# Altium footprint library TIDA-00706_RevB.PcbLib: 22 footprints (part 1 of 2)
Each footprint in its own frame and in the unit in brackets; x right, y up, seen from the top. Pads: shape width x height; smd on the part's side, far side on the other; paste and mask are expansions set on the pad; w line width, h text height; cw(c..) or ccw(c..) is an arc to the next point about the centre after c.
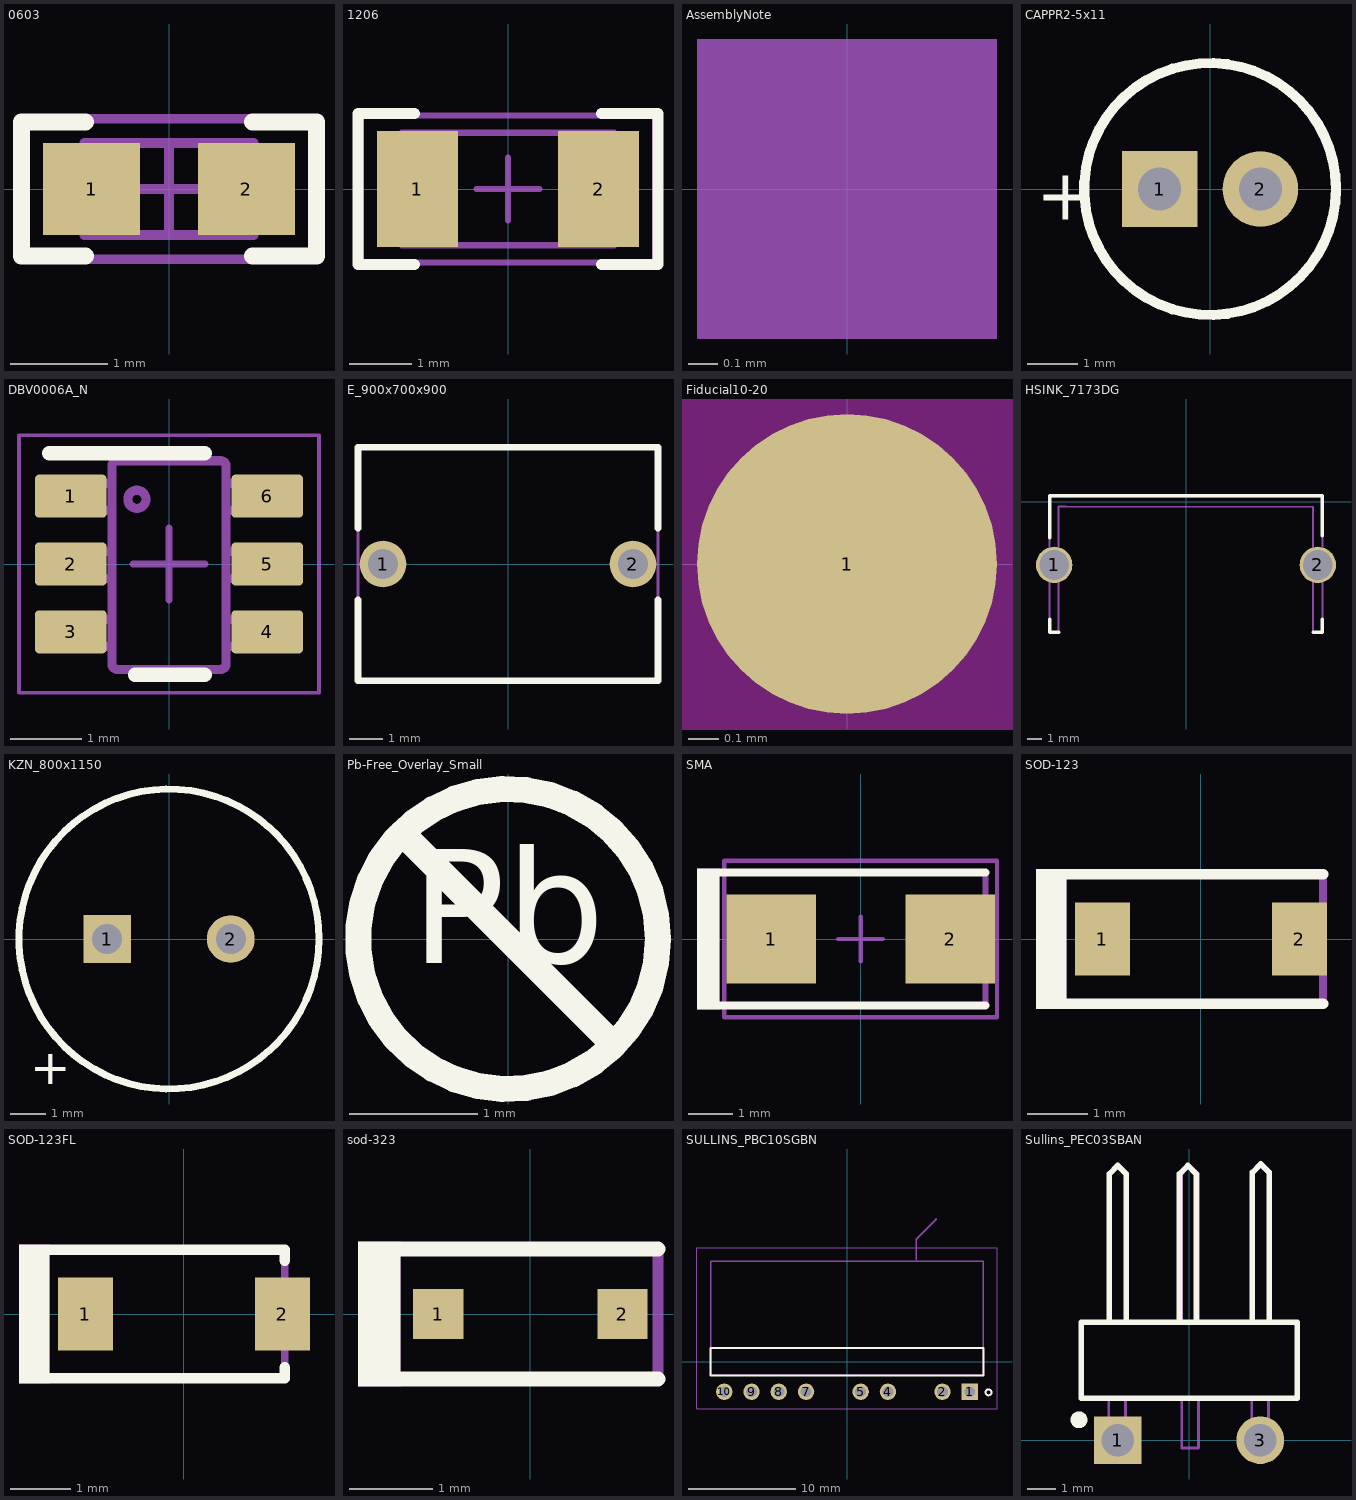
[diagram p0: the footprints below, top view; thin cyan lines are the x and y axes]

## 0603 [mm] "0603 from SM-752 data"
height 1
pads (2):
  rect 1x0.95 smd: 1(-0.8,0) 2(0.8,0)
Top Overlay:
  lines w0.178: -0.864,-0.691 -1.524,-0.691 -1.524,0.693 -0.864,0.693 ; 0.864,-0.691 1.524,-0.691 1.524,0.693 0.864,0.693
Mechanical 5:
  lines w0.1: -1.55,-0.725 1.55,-0.725 1.55,0.725 -1.55,0.725 -1.55,-0.725
  text ".Designator" at -0.991,-0.381 h0.76
Mechanical 13:
  lines w0.1: -0.55,-0.475 -0.55,0.475 ; 0.55,-0.475 0.55,0.475 ; -0.875,-0.475 -0.875,0.475 0.875,0.475 0.875,-0.475 -0.875,-0.475
Mechanical 15:
  lines w0.1: -0.475,0 0.475,0 ; 0,-0.475 0,0.475 ; -1.55,-0.725 -1.55,0.725 1.55,0.725 1.55,-0.725 -1.55,-0.725
3D body: height 1, standoff 0, extent 0.551,-0.474 0.874,0.474
3D body: height 1, standoff 0, extent -0.549,-0.474 0.549,0.474
3D body: height 1, standoff 0, extent -0.874,-0.474 -0.551,0.474

## 1206 [mm] "1206 from SM-752 data"
height 1.35
pads (2):
  rect 1.3x1.85 smd: 1(-1.45,0) 2(1.45,0)
Top Overlay:
  lines w0.178: -1.5,-1.21 -2.4,-1.21 -2.4,1.21 -1.5,1.21 ; 1.5,-1.21 2.4,-1.21 2.4,1.21 1.5,1.21
Mechanical 5:
  lines w0.1: -1.7,-0.9 -1.7,0.9 1.7,0.9 1.7,-0.9 -1.7,-0.9
  text ".Designator" at -0.965,-0.457 h0.76
Mechanical 13:
  lines w0.1: -1.2,-0.9 -1.2,0.9 ; 1.2,-0.9 1.2,0.9 ; -1.7,-0.9 -1.7,0.9 1.7,0.9 1.7,-0.9 -1.7,-0.9
Mechanical 15:
  lines w0.1: -0.5,0 0.5,0 ; 0,-0.5 0,0.5 ; -2.35,-1.175 -2.35,1.175 2.35,1.175 2.35,-1.175 -2.35,-1.175
3D body: height 1.35, standoff 0, extent 1.201,-0.899 1.699,0.899
3D body: height 1.35, standoff 0, extent -1.199,-0.899 1.199,0.899
3D body: height 1.35, standoff 0, extent -1.699,-0.899 -1.201,0.899

## AssemblyNote [mm] "Assembly Note"
Mechanical 5:
  rectangle: -0.508,-0.508 0.508,0.508
  text ".Comment" at 1.143,-0.508 h0.76
  text ".Designator" at -4.191,-0.508 h0.76

## CAPPR2-5x11 [mm] "Capacitor, Electrolytic, Radial; Body 5 x 11 mm (Dia.xH typ); Pin Spacing 2 mm (typ)"
height 11.5
pads (2):
  rect 1.5x1.5 hole 0.85: 1(-1,0)
  round 1.5 hole 0.85: 2(1,0)
Top Overlay:
  circle w0.2: c0,0 r2.5
  text "+" at -3.454,-0.61 h1.02
Mechanical 5:
  circle w0.127: c0,0 r2.5
  text "+" at -3.353,-0.533 h1.02
  text ".Designator" at 0.61,0.254 h0.76
3D body: height 11.29, standoff -3.51, extent -2.525,-2.527 2.526,2.523

## DBV0006A_N [mm] "SOT23, 6-Leads, Body 2.9x1.6mm, Pitch 0.95mm, Lead Span 2.8mm, IPC Medium Density"
height 1.45
pads (6):
  rrect17% 1x0.6 smd: 1(-1.375,0.95) 2(-1.375,0) 3(-1.375,-0.95) 4(1.375,-0.95) 5(1.375,0) 6(1.375,0.95)
Top Overlay:
  lines w0.2: -1.675,1.55 0.5,1.55 ; -0.475,-1.55 0.5,-1.55
Mechanical 5:
  lines w0.127: 0.724,-1.475 ccw(c0.723,-1.399) 0.8,-1.399 0.799,1.37 ccw(c0.723,1.37) 0.724,1.446 ; 0.723,-1.475 -0.725,-1.475 -0.725,-1.475 cw(c-0.724,-1.399) -0.801,-1.399 -0.801,1.37 cw(c-0.724,1.37) -0.725,1.446 -0.725,1.446 0.723,1.446 ; 0.723,-1.475 0.724,-1.475 ; 0.723,1.446 0.724,1.446 ; -1.423,-1.154 -1.423,-0.78 -1.206,-0.78 -1.113,-0.78 -1.081,-0.78 -0.828,-0.78 -0.801,-0.78 -0.801,-1.154 -0.828,-1.154 -1.081,-1.154 -1.113,-1.154 -1.206,-1.154 -1.423,-1.154 ; -1.423,-0.202 -1.423,0.173 -1.206,0.173 -1.113,0.173 -1.081,0.173 -0.828,0.173 -0.801,0.173 -0.801,-0.202 -0.828,-0.202 -1.081,-0.202 -1.113,-0.202 -1.206,-0.202 -1.423,-0.202 ; -1.423,0.751 -1.423,1.125 -1.206,1.125 -1.113,1.125 -1.081,1.125 -0.828,1.125 -0.801,1.125 -0.801,0.751 -0.828,0.751 -1.081,0.751 -1.113,0.751 -1.206,0.751 -1.423,0.751 ; -0.577,0.906 ccw(c-0.45,0.906) -0.323,0.906 ccw(c-0.45,0.906) -0.577,0.906 ; 0.799,-1.154 0.799,-0.78 0.827,-0.78 1.08,-0.78 1.112,-0.78 1.205,-0.78 1.422,-0.78 1.422,-1.154 1.205,-1.154 1.112,-1.154 1.08,-1.154 0.827,-1.154 0.799,-1.154 ; 0.799,-0.202 0.799,0.173 0.827,0.173 1.08,0.173 1.112,0.173 1.205,0.173 1.422,0.173 1.422,-0.202 1.205,-0.202 1.112,-0.202 1.08,-0.202 0.827,-0.202 0.799,-0.202 ; 0.799,0.751 0.799,1.125 0.827,1.125 1.08,1.125 1.112,1.125 1.205,1.125 1.422,1.125 1.422,0.751 1.205,0.751 1.112,0.751 1.08,0.751 0.827,0.751 0.799,0.751
  text ".Designator" at -0.317,0.432 h0.76
Mechanical 15:
  lines w0.05: -2.1,-1.8 -2.1,1.8 2.1,1.8 2.1,-1.8 -2.1,-1.8
  lines w0.1: -0.5,0 0.5,0 ; 0,-0.5 0,0.5
3D body: height 1.12, standoff 0, extent -1.422,-1.46 1.423,1.461

## E_900x700x900 [mm] "TH, 2- Leads, Body 9x7mm, Pin Spacing 7.5mm"
height 12
pads (2):
  round 1.4 hole 0.9: 1(-3.75,0) 2(3.75,0)
Top Overlay:
  lines w0.2: -4.5,-1.071 -4.5,-3.5 4.5,-3.5 4.5,-1.071 ; -4.5,1.071 -4.5,3.5 4.5,3.5 4.5,1.071
Mechanical 5:
  lines w0.1: -4.5,-3.5 4.5,-3.5 4.5,3.5 -4.5,3.5 -4.5,-3.5
  text ".Designator" at -1.397,-0.406 h0.76
3D body: height 0.3, standoff -2.5, extent -4.047,-0.299 -3.45,0.3
3D body: height 1.36, standoff -0.16, extent -4.047,-1.732 -3.45,0.3
3D body: height 6.12, standoff 0.81, extent -4.047,-1.732 -1.545,-1.033
3D body: height 6.12, standoff 0.81, extent 1.546,1.033 4.048,1.732
3D body: height 1.36, standoff -0.16, extent 3.45,-0.299 4.048,1.732
3D body: height 0.3, standoff -2.5, extent 3.45,-0.299 4.048,0.299
3D body: height 11.96, standoff 3, extent -4.491,-3.5 4.491,3.5

## Fiducial10-20 [mm]
pads (1):
  round 1 smd mask+0.5: 1(0,0)
Top Layer keep-out:
  circle w1.178: c0,0 r0.5

## HSINK_7173DG [mil] "Aavid"
height 900
pads (2):
  round 100 hole 82: 1(-362.5,-173.23) 2(362.5,-173.23)
Top Overlay:
  lines w10: -375,-323.23 -375,-358.23 -350,-358.23 ; -375,-98.23 -375,16.77 375,16.77 375,-93.23 ; 350,-358.23 375,-358.23 375,-323.23
Mechanical 5:
  lines w5: -375,-358.27 -375,14.27 375,14.27 375,-358.27 349.41,-358.27 349.41,-82.68 349.41,-13.78 -329.72,-12.8 -350.39,-12.8 -350.39,-31.5 -350.39,-358.27 -375,-358.27
  text ".Designator" at -19,23 h30
3D body: height 150, standoff 0, extent 349.81,-247.74 374.81,-97.74
3D body: height 150, standoff 0, extent -375,-248.23 -350,-98.23
3D body: height 0, standoff -100, extent 349.49,-192.99 375.15,-155.49
3D body: height 0, standoff -100, extent -375.24,-190.73 -349.59,-153.23
3D body: height 900, standoff 150, extent -375.49,-358.23 375.3,12.26

## KZN_800x1150 [mm] "TH, 2-Leads, Dia 8mm"
height 13
pads (2):
  rect 1.35x1.35 hole 0.85: 1(-1.75,0)
  round 1.35 hole 0.85: 2(1.75,0)
Top Overlay:
  circle w0.2: c0,0 r4.25
  text "+" at -3.937,-4.115 h1
  text "+" at -3.937,-4.115 h1
Mechanical 5:
  circle w0.1: c0,0 r4.25
  text ".Designator" at -0.838,-0.33 h0.76
  text "+" at -4.064,3.048 h1.02
  text "+" at -4.064,3.048 h1.02
3D body: height 0, standoff -2, extent 1.453,-0.299 2.05,0.3
3D body: height 0, standoff -2.5, extent -2.047,-0.299 -1.45,0.3
3D body: height 13.01, standoff -4, extent -4.217,-4.243 4.244,4.243

## Pb-Free_Overlay_Small [mm]
Top Overlay:
  circle w0.203: c0,0 r1.168
  lines w0.203: -0.826,0.826 0.826,-0.826
  text "Pb" at -0.752,-0.48 h1.52

## SMA [mm] "Molded Diode, 2-Leads, Body 4.3x2.6mm, IPC Medium Density, based on OnSemi component dimensions and land pattern"
height 2.27
pads (2):
  rect 2x2 smd: 1(-2,0) 2(2,0)
Top Overlay:
  rectangle: -3.658,-1.575 -3.15,1.575
  lines w0.178: -3.327,-1.486 2.794,-1.486 ; -3.327,1.486 2.794,1.486
Mechanical 5:
  rectangle: -3.658,-1.575 -3.15,1.575
  lines w0.127: -3.327,-1.486 2.794,-1.486 2.794,1.486 -3.327,1.486
  text ".Designator" at -1.168,-0.508 h0.76
Mechanical 15:
  lines w0.1: -0.5,0 0.5,0 ; 0,-0.5 0,0.5 ; -3.05,-1.75 -3.05,1.75 3.05,1.75 3.05,-1.75 -3.05,-1.75
3D body: height 2.42, standoff 0.02, extent -2.6,-1.3 2.6,1.3

## SOD-123 [mm] "On Semi recommended land pattern"
height 1.35
pads (2):
  rect 0.915x1.22 smd: 1(-1.637,0) 2(1.637,0)
Top Overlay:
  rectangle: -2.743,-1.168 -2.235,1.168
  lines w0.178: -2.413,-1.079 2.032,-1.079 ; -2.413,1.079 2.032,1.079
Mechanical 5:
  rectangle: -2.743,-1.168 -2.235,1.168
  lines w0.127: -2.413,-1.079 2.032,-1.079 2.032,1.079 -2.413,1.079
  text ".Designator" at -1.372,-0.279 h0.76
3D body: height 1.35, standoff 0, extent -1.932,-0.9 1.932,0.9

## SOD-123FL [mm] "Copied from SOD-123"
height 0.991
pads (2):
  rect 0.915x1.22 smd: 1(-1.637,0) 2(1.637,0)
Top Overlay:
  rectangle: -2.743,-1.156 -2.235,1.156
  lines w0.178: -2.438,-1.067 1.676,-1.067 1.676,-0.889 ; -2.438,1.067 1.676,1.067 1.676,0.889
Mechanical 5:
  rectangle: -2.743,-1.156 -2.235,1.156
  lines w0.127: -2.438,-1.067 1.676,-1.067 1.676,1.067 -2.438,1.067
  text ".Designator" at -1.422,-0.305 h0.76
3D body: height 1, standoff 0, extent -1.9,-0.9 1.9,0.9

## sod-323 [mm] "NXP recommended land pattern"
height 1.15
pads (2):
  rect 0.6x0.6 smd paste-0.05: 1(-1.1,0) 2(1.1,0)
Top Overlay:
  rectangle: -2.057,-0.864 -1.549,0.864
  lines w0.178: -1.803,-0.775 0.1,-0.775 1.525,-0.775 ; -1.803,0.775 0.1,0.775 1.525,0.775
Mechanical 5:
  rectangle: -2.057,-0.864 -1.549,0.864
  lines w0.127: -1.803,-0.775 0.1,-0.775 1.525,-0.775 1.525,0.775 0.1,0.775 -1.803,0.775
  text ".Designator" at 0.432,0.305 h0.76
3D body: height 1.1, standoff 0, extent -1.3,-0.675 1.3,0.675

## SULLINS_PBC10SGBN [mil] "CONN,MALE-10PIN 2.54MM PITCH,SINGLEROW,SULLINS"
height 145.28
pads (10):
  rect 60x60 / inner round 60 / far side rect 60x60 hole 40: 1(450,-109.84)
  round 60 hole 40: 2(350,-109.84) 4(150,-109.84) 5(50,-109.84) 7(-150,-109.84) 8(-250,-109.84) 9(-350,-109.84) 10(-450,-109.84)
  round 0 all layers, no hole mask+0: 3(250,-109.84) 6(-50,-109.84)
Top Overlay:
  circle w7: c519,-112 r11
  lines w7.01: -500,-50 500,-50 500,50 -500,50 -500,-50
Bottom Overlay:
  lines w7: -473.63,50.16 -434.26,50.16 ; -400.89,-50 -361.52,-50 ; -394.89,50.16 -355.52,50.16 ; -316.15,50.16 -276.78,50.16 ; -243.41,-50 -204.04,-50 ; -237.41,50.16 -198.04,50.16 ; -164.67,-50 -125.3,-50 ; -158.67,50.16 -119.3,50.16 ; -85.93,-50 -46.56,-50 ; -79.93,50.16 -40.56,50.16 ; -7.19,-50 32.18,-50 ; -1.19,50.16 38.18,50.16 ; 71.55,-50 110.92,-50 ; 77.55,50.16 116.92,50.16 ; 150.29,-50 189.66,-50 ; 156.29,50.16 195.66,50.16 ; 229.03,-50 268.4,-50 ; 235.03,50.16 274.4,50.16 ; 307.77,-50 347.14,-50 ; 313.77,50.16 353.14,50.16 ; 386.51,-50 425.88,-50 ; 392.51,50.16 431.88,50.16 ; 500,-19.21 500,20.16
Mechanical 5:
  circle w5: c450,-109.84 r11
  lines w5: -500,-50 500,-50 500,50 ; -500,-49.61 -500,50 ; -500,50 500,50 ; -500,50 -500,368.11 500.01,368.11 500.01,50.01
  text ".Designator" at 134,7 h30
Mechanical 15:
  lines w1.97: -550,-172.52 -550,418.11 550,418.11 550,-172.52 -550,-172.52
Mechanical 16:
  lines w7: 254,374.16 254,450.16 327,523.16
Mechanical 17:
  text "PCE EDGE THIS SIDE" at 337,517.16 h40
  text "LEAD LENGTH:5.08MM" at -327,74.16 h40
3D body: height 141.73, standoff -198.27, extent -499.99,-122.49 500.01,368.01

## Sullins_PEC03SBAN [mm] "Sullins"
height 3.556
pads (3):
  rect 1.7x1.7 hole 1.16: 1(-2.54,0)
  round 0 all layers, no hole mask+0: 2(0,0)
  round 1.7 hole 1.16: 3(2.54,0)
Top Overlay:
  circle w0.3: c-3.925,0.725 r0.15
  lines w0.2: -2.84,4.2 -2.84,9 -2.84,9.5 -2.54,9.8 -2.24,9.5 -2.24,4.2 ; -0.34,4.2 -0.34,9 -0.34,9.5 -0.04,9.8 0.26,9.5 0.26,4.2 ; 2.26,4.25 2.26,9.05 2.26,9.55 2.56,9.85 2.86,9.55 2.86,4.25 ; -3.84,1.5 -3.84,4 -3.84,4.2 3.86,4.2 3.86,4 3.86,1.5 -3.84,1.5
Mechanical 5:
  lines w0.1: -2.86,1.5 -2.86,-0.3 -2.26,-0.3 -2.26,1.5 ; -2.86,4.2 -2.86,9.525 -2.56,9.85 -2.26,9.55 -2.26,4.2 ; -0.26,1.5 -0.26,-0.275 0.34,-0.275 0.34,1.5 ; -0.26,4.2 -0.26,9.475 0.04,9.8 0.34,9.5 0.34,4.2 ; 2.24,1.5 2.24,-0.25 2.84,-0.275 2.84,1.5 ; 2.24,4.2 2.24,9.45 2.54,9.775 2.84,9.5 2.84,4.2 ; -3.86,1.5 3.84,1.5 3.84,4.2 -3.86,4.2 -3.86,1.5
  text ".Designator" at 0.33,2.845 h0.76
3D body: height 3.56, standoff -2.54, extent -3.81,-0.287 3.81,9.937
